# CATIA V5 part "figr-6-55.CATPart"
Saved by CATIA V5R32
Part number: Part1
Bounding box of the stored display mesh (mm): x -50.648 to 50.648, y -72.183 to 72.183, z 0 to 52
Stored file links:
  D:\PROJECTS\Project 2022\CATIA V5 6R 2022\Resources\Part Files\c06_catia_v5_6r2022_prt\figr-6-55.CATPart
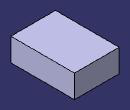
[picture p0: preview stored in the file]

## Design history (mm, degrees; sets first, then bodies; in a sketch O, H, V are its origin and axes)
Body1 (main body)
  Sketch1 on xy-plane, origin (0, 0, 0), H (1, 0, 0), V (0, 1, 0)
    line L1 (-50.6478, 72.1832) -> (50.6478, 72.1832)
    line L2 (50.6478, 72.1832) -> (50.6478, -72.1832)
    line L3 (50.6478, -72.1832) -> (-50.6478, -72.1832)
    line L4 (-50.6478, -72.1832) -> (-50.6478, 72.1832)
    axis line L5 (50.6478, -72.1832) -> (-50.6478, 72.1832)
    horizontal: L1 H, L3 H
    vertical: L2 V, L4 V
    midpoint: O L5
  Pad1: profile Sketch1, direction (0, 0, 1), length 52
